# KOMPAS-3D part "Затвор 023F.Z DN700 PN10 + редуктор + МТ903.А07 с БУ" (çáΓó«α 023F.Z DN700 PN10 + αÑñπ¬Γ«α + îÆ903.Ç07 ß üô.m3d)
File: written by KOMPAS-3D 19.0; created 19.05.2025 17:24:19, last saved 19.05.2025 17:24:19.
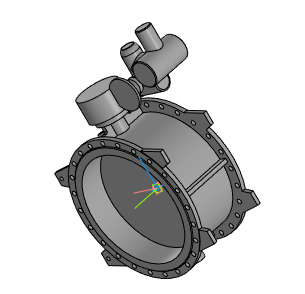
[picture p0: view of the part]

Document properties: Полное имя файла: Затвор 023F.Z DN700 PN10 + редуктор + МТ903.А07 с БУ.a3d

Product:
- Part/product: Затвор 023F.Z DN700 PN10 + редуктор + МТ903.А07 с БУ
    Масса: 675.919

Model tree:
1. Операция без истории:1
